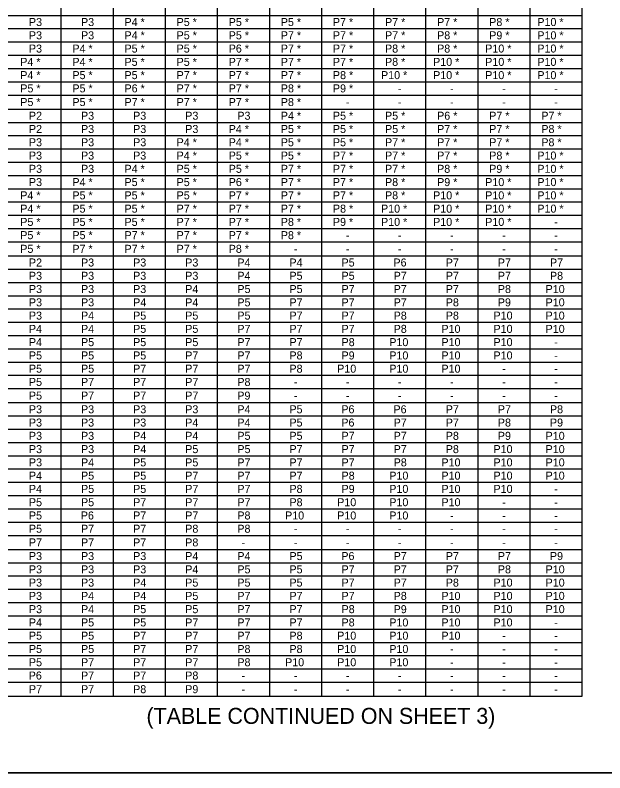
# Model space of a CAD drawing. Extents: x 637580 to 641008, y 294594 to 295782.
# Drawn here: x 638664.4 to 638885.2, y 295202.6 to 295486.5 of the extents above; entities that cross this region are included whole.
import ezdxf

# ---------------------------------------------------------------- set-up
doc = ezdxf.new("R2010")
doc.units = 0
for name, color, linetype in [('1', 7, 'Continuous'), ('2', 7, 'Continuous'), ('3', 7, 'Continuous')]:
    doc.layers.add(name, color=color, linetype=linetype)

msp = doc.modelspace()

# ---------------------------------------------------------------- linework, layer by layer
at = {"layer": '1'}
for p, q in [((638876.73, 295231.34), (638876.73, 295750.63)), ((638681.66, 295231.34), (638681.66, 295735.61)), ((638701.17, 295231.34), (638701.17, 295735.61)), ((638720.67, 295231.34), (638720.67, 295735.61)), ((638740.18, 295231.34), (638740.18, 295735.61)), ((638759.69, 295231.34), (638759.69, 295735.61)), ((638779.2, 295231.34), (638779.2, 295735.61)), ((638798.7, 295231.34), (638798.7, 295735.61)), ((638818.21, 295231.34), (638818.21, 295735.61)), ((638837.72, 295231.34), (638837.72, 295735.61)), ((638857.23, 295231.34), (638857.23, 295735.61)), ((638509.81, 295451.3), (638876.73, 295451.3)), ((638509.81, 295396.31), (638876.73, 295396.31)), ((638509.81, 295341.32), (638876.73, 295341.32)), ((638509.81, 295286.33), (638876.73, 295286.33)), ((638509.81, 295231.34), (638876.73, 295231.34)), ((639247.31, 295202.63), (638461.31, 295202.63)), ((638461.31, 295202.63), (639047.31, 295202.63))]:
    msp.add_line(p, q, dxfattribs=at)
at = {"layer": '2'}
for p, q in [((638536.61, 295486.4), (638876.73, 295486.4)), ((638536.61, 295481.43), (638876.73, 295481.43)), ((638536.61, 295476.45), (638876.73, 295476.45)), ((638536.61, 295471.48), (638876.73, 295471.48)), ((638536.61, 295466.51), (638876.73, 295466.51)), ((638536.61, 295461.54), (638876.73, 295461.54)), ((638536.61, 295456.56), (638876.73, 295456.56)), ((638536.61, 295446.33), (638876.73, 295446.33)), ((638536.61, 295441.35), (638876.73, 295441.35)), ((638536.61, 295436.38), (638876.73, 295436.38)), ((638536.61, 295431.41), (638876.73, 295431.41)), ((638536.61, 295426.44), (638876.73, 295426.44)), ((638536.61, 295421.46), (638876.73, 295421.46)), ((638536.61, 295416.49), (638876.73, 295416.49)), ((638536.61, 295411.52), (638876.73, 295411.52)), ((638536.61, 295406.55), (638876.73, 295406.55)), ((638536.61, 295401.57), (638876.73, 295401.57)), ((638536.61, 295391.34), (638876.73, 295391.34)), ((638536.61, 295386.36), (638876.73, 295386.36)), ((638536.61, 295381.39), (638876.73, 295381.39)), ((638536.61, 295376.42), (638876.73, 295376.42)), ((638536.61, 295371.45), (638876.73, 295371.45)), ((638536.61, 295366.47), (638876.73, 295366.47)), ((638536.61, 295361.5), (638876.73, 295361.5)), ((638536.61, 295356.53), (638876.73, 295356.53)), ((638536.61, 295351.56), (638876.73, 295351.56)), ((638536.61, 295346.58), (638876.73, 295346.58)), ((638536.61, 295336.35), (638876.73, 295336.35)), ((638536.61, 295331.37), (638876.73, 295331.37)), ((638536.61, 295326.4), (638876.73, 295326.4)), ((638536.61, 295321.43), (638876.73, 295321.43)), ((638536.61, 295316.46), (638876.73, 295316.46)), ((638536.61, 295311.48), (638876.73, 295311.48)), ((638536.61, 295306.51), (638876.73, 295306.51)), ((638536.61, 295301.54), (638876.73, 295301.54)), ((638536.61, 295296.57), (638876.73, 295296.57)), ((638536.61, 295291.59), (638876.73, 295291.59)), ((638536.61, 295281.36), (638876.73, 295281.36)), ((638536.61, 295276.38), (638876.73, 295276.38)), ((638536.61, 295271.41), (638876.73, 295271.41)), ((638536.61, 295266.44), (638876.73, 295266.44)), ((638536.61, 295261.47), (638876.73, 295261.47)), ((638536.61, 295256.49), (638876.73, 295256.49)), ((638536.61, 295251.52), (638876.73, 295251.52)), ((638536.61, 295246.55), (638876.73, 295246.55)), ((638536.61, 295241.58), (638876.73, 295241.58)), ((638536.61, 295236.6), (638876.73, 295236.6))]:
    msp.add_line(p, q, dxfattribs=at)

# ---------------------------------------------------------------- texts
at = {"layer": '1'}
for s, p in [('P3', (638669.56, 295482.41)), ('P3', (638689.06, 295482.41)), ('P4 *', (638705.34, 295482.41)), ('P5 *', (638724.85, 295482.41)), ('P5 *', (638744.35, 295482.41)), ('P5 *', (638763.86, 295482.41)), ('P7 *', (638783.37, 295482.41)), ('P7 *', (638802.88, 295482.41)), ('P7 *', (638822.38, 295482.41)), ('P8 *', (638841.89, 295482.41)), ('P10 *', (638859.9, 295482.41)), ('P3', (638669.56, 295477.44)), ('P3', (638689.06, 295477.44)), ('P4 *', (638705.34, 295477.44)), ('P5 *', (638724.85, 295477.44)), ('P5 *', (638744.35, 295477.44)), ('P7 *', (638763.86, 295477.44)), ('P7 *', (638783.37, 295477.44)), ('P7 *', (638802.88, 295477.44)), ('P8 *', (638822.38, 295477.44)), ('P9 *', (638841.89, 295477.44)), ('P10 *', (638859.9, 295477.44)), ('P3', (638669.56, 295472.47)), ('P4 *', (638685.83, 295472.47)), ('P5 *', (638705.34, 295472.47)), ('P5 *', (638724.85, 295472.47)), ('P6 *', (638744.35, 295472.47)), ('P7 *', (638763.86, 295472.47)), ('P7 *', (638783.37, 295472.47)), ('P8 *', (638802.88, 295472.47)), ('P8 *', (638822.38, 295472.47)), ('P10 *', (638840.39, 295472.47)), ('P10 *', (638859.9, 295472.47)), ('P4 *', (638666.32, 295467.49)), ('P4 *', (638685.83, 295467.49)), ('P5 *', (638705.34, 295467.49)), ('P5 *', (638724.85, 295467.49)), ('P7 *', (638744.35, 295467.49)), ('P7 *', (638763.86, 295467.49)), ('P7 *', (638783.37, 295467.49)), ('P8 *', (638802.88, 295467.49)), ('P10 *', (638820.88, 295467.49)), ('P10 *', (638840.39, 295467.49)), ('P10 *', (638859.9, 295467.49)), ('P4 *', (638666.32, 295462.52)), ('P5 *', (638685.83, 295462.52)), ('P5 *', (638705.34, 295462.52)), ('P7 *', (638724.85, 295462.52)), ('P7 *', (638744.35, 295462.52)), ('P7 *', (638763.86, 295462.52)), ('P8 *', (638783.37, 295462.52)), ('P10 *', (638801.38, 295462.52)), ('P10 *', (638820.88, 295462.52)), ('P10 *', (638840.39, 295462.52)), ('P10 *', (638859.9, 295462.52)), ('P5 *', (638666.32, 295457.55)), ('P5 *', (638685.83, 295457.55)), ('P6 *', (638705.34, 295457.55)), ('P7 *', (638724.85, 295457.55)), ('P7 *', (638744.35, 295457.55)), ('P8 *', (638763.86, 295457.55)), ('P9 *', (638783.37, 295457.55)), ('-', (638807.73, 295457.55)), ('-', (638827.23, 295457.55)), ('-', (638846.74, 295457.55)), ('-', (638866.25, 295457.55)), ('P5 *', (638666.32, 295452.43)), ('P5 *', (638685.83, 295452.43)), ('P7 *', (638705.34, 295452.43)), ('P7 *', (638724.85, 295452.43)), ('P7 *', (638744.35, 295452.43)), ('P8 *', (638763.86, 295452.43)), ('-', (638788.22, 295452.43)), ('-', (638807.73, 295452.43)), ('-', (638827.23, 295452.43)), ('-', (638846.74, 295452.43)), ('-', (638866.25, 295452.43)), ('P2', (638669.56, 295447.31)), ('P3', (638689.06, 295447.31)), ('P3', (638708.57, 295447.31)), ('P3', (638728.08, 295447.31)), ('P3', (638747.59, 295447.31)), ('P4 *', (638763.86, 295447.31)), ('P5 *', (638783.37, 295447.31)), ('P5 *', (638802.88, 295447.31)), ('P6 *', (638822.38, 295447.31)), ('P7 *', (638841.89, 295447.31)), ('P7 *', (638861.4, 295447.31)), ('P2', (638669.56, 295442.34)), ('P3', (638689.06, 295442.34)), ('P3', (638708.57, 295442.34)), ('P3', (638728.08, 295442.34)), ('P4 *', (638744.35, 295442.34)), ('P5 *', (638763.86, 295442.34)), ('P5 *', (638783.37, 295442.34)), ('P5 *', (638802.88, 295442.34)), ('P7 *', (638822.38, 295442.34)), ('P7 *', (638841.89, 295442.34)), ('P8 *', (638861.4, 295442.34)), ('P3', (638669.56, 295437.37)), ('P3', (638689.06, 295437.37)), ('P3', (638708.57, 295437.37)), ('P4 *', (638724.85, 295437.37)), ('P4 *', (638744.35, 295437.37)), ('P5 *', (638763.86, 295437.37)), ('P5 *', (638783.37, 295437.37)), ('P7 *', (638802.88, 295437.37)), ('P7 *', (638822.38, 295437.37)), ('P7 *', (638841.89, 295437.37)), ('P8 *', (638861.4, 295437.37)), ('P3', (638669.56, 295432.39)), ('P3', (638689.06, 295432.39)), ('P3', (638708.57, 295432.39)), ('P4 *', (638724.85, 295432.39)), ('P5 *', (638744.35, 295432.39)), ('P5 *', (638763.86, 295432.39)), ('P7 *', (638783.37, 295432.39)), ('P7 *', (638802.88, 295432.39)), ('P7 *', (638822.38, 295432.39)), ('P8 *', (638841.89, 295432.39)), ('P10 *', (638859.9, 295432.39)), ('P3', (638669.56, 295427.42)), ('P3', (638689.06, 295427.42)), ('P4 *', (638705.34, 295427.42)), ('P5 *', (638724.85, 295427.42)), ('P5 *', (638744.35, 295427.42)), ('P7 *', (638763.86, 295427.42)), ('P7 *', (638783.37, 295427.42)), ('P7 *', (638802.88, 295427.42)), ('P8 *', (638822.38, 295427.42)), ('P9 *', (638841.89, 295427.42)), ('P10 *', (638859.9, 295427.42)), ('P3', (638669.56, 295422.45)), ('P4 *', (638685.83, 295422.45)), ('P5 *', (638705.34, 295422.45)), ('P5 *', (638724.85, 295422.45)), ('P6 *', (638744.35, 295422.45)), ('P7 *', (638763.86, 295422.45)), ('P7 *', (638783.37, 295422.45)), ('P8 *', (638802.88, 295422.45)), ('P9 *', (638822.38, 295422.45)), ('P10 *', (638840.39, 295422.45)), ('P10 *', (638859.9, 295422.45)), ('P4 *', (638666.32, 295417.48)), ('P5 *', (638685.83, 295417.48)), ('P5 *', (638705.34, 295417.48)), ('P5 *', (638724.85, 295417.48)), ('P7 *', (638744.35, 295417.48)), ('P7 *', (638763.86, 295417.48)), ('P7 *', (638783.37, 295417.48)), ('P8 *', (638802.88, 295417.48)), ('P10 *', (638820.88, 295417.48)), ('P10 *', (638840.39, 295417.48)), ('P10 *', (638859.9, 295417.48)), ('P4 *', (638666.32, 295412.5)), ('P5 *', (638685.83, 295412.5)), ('P5 *', (638705.34, 295412.5)), ('P7 *', (638724.85, 295412.5)), ('P7 *', (638744.35, 295412.5)), ('P7 *', (638763.86, 295412.5)), ('P8 *', (638783.37, 295412.5)), ('P10 *', (638801.38, 295412.5)), ('P10 *', (638820.88, 295412.5)), ('P10 *', (638840.39, 295412.5)), ('P10 *', (638859.9, 295412.5)), ('P5 *', (638666.32, 295407.53)), ('P5 *', (638685.83, 295407.53)), ('P5 *', (638705.34, 295407.53)), ('P7 *', (638724.85, 295407.53)), ('P7 *', (638744.35, 295407.53)), ('P8 *', (638763.86, 295407.53)), ('P9 *', (638783.37, 295407.53)), ('P10 *', (638801.38, 295407.53)), ('P10 *', (638820.88, 295407.53)), ('P10 *', (638840.39, 295407.53)), ('-', (638866.25, 295407.53)), ('P5 *', (638666.32, 295402.56)), ('P5 *', (638685.83, 295402.56)), ('P7 *', (638705.34, 295402.56)), ('P7 *', (638724.85, 295402.56)), ('P7 *', (638744.35, 295402.56)), ('P8 *', (638763.86, 295402.56)), ('-', (638788.22, 295402.56)), ('-', (638807.73, 295402.56)), ('-', (638827.23, 295402.56)), ('-', (638846.74, 295402.56)), ('-', (638866.25, 295402.56)), ('P5 *', (638666.32, 295397.44)), ('P7 *', (638685.83, 295397.44)), ('P7 *', (638705.34, 295397.44)), ('P7 *', (638724.85, 295397.44)), ('P8 *', (638744.35, 295397.44)), ('-', (638768.71, 295397.44)), ('-', (638788.22, 295397.44)), ('-', (638807.73, 295397.44)), ('-', (638827.23, 295397.44)), ('-', (638846.74, 295397.44)), ('-', (638866.25, 295397.44)), ('P2', (638669.56, 295392.32)), ('P3', (638689.06, 295392.32)), ('P3', (638708.57, 295392.32)), ('P3', (638728.08, 295392.32)), ('P4', (638747.59, 295392.32)), ('P4', (638767.09, 295392.32)), ('P5', (638786.6, 295392.32)), ('P6', (638806.03, 295392.32)), ('P7', (638825.62, 295392.32)), ('P7', (638845.12, 295392.32)), ('P7', (638864.63, 295392.32)), ('P3', (638669.56, 295387.35)), ('P3', (638689.06, 295387.35)), ('P3', (638708.57, 295387.35)), ('P3', (638728.08, 295387.35)), ('P4', (638747.59, 295387.35)), ('P5', (638767.09, 295387.35)), ('P5', (638786.6, 295387.35)), ('P7', (638806.11, 295387.35)), ('P7', (638825.62, 295387.35)), ('P7', (638845.12, 295387.35)), ('P8', (638864.63, 295387.35)), ('P3', (638669.56, 295382.38)), ('P3', (638689.06, 295382.38)), ('P3', (638708.57, 295382.38)), ('P4', (638728.08, 295382.38)), ('P5', (638747.59, 295382.38)), ('P5', (638767.09, 295382.38)), ('P7', (638786.6, 295382.38)), ('P7', (638806.11, 295382.38)), ('P7', (638825.62, 295382.38)), ('P8', (638845.12, 295382.38)), ('P10', (638863, 295382.38)), ('P3', (638669.56, 295377.4)), ('P3', (638689.06, 295377.4)), ('P4', (638708.57, 295377.4)), ('P4', (638728.08, 295377.4)), ('P5', (638747.59, 295377.4)), ('P7', (638767.09, 295377.4)), ('P7', (638786.6, 295377.4)), ('P7', (638806.11, 295377.4)), ('P8', (638825.62, 295377.4)), ('P9', (638845.11, 295377.4)), ('P10', (638863, 295377.4)), ('P3', (638669.56, 295372.43)), ('P4', (638689.06, 295372.43)), ('P5', (638708.57, 295372.43)), ('P5', (638728.08, 295372.43)), ('P5', (638747.59, 295372.43)), ('P7', (638767.09, 295372.43)), ('P7', (638786.6, 295372.43)), ('P8', (638806.11, 295372.43)), ('P8', (638825.62, 295372.43)), ('P10', (638843.49, 295372.43)), ('P10', (638863, 295372.43)), ('P4', (638669.56, 295367.46)), ('P4', (638689.06, 295367.46)), ('P5', (638708.57, 295367.46)), ('P5', (638728.08, 295367.46)), ('P7', (638747.59, 295367.46)), ('P7', (638767.09, 295367.46)), ('P7', (638786.6, 295367.46)), ('P8', (638806.11, 295367.46)), ('P10', (638823.99, 295367.46)), ('P10', (638843.49, 295367.46)), ('P10', (638863, 295367.46)), ('P4', (638669.56, 295362.49)), ('P5', (638689.06, 295362.49)), ('P5', (638708.57, 295362.49)), ('P5', (638728.08, 295362.49)), ('P7', (638747.59, 295362.49)), ('P7', (638767.09, 295362.49)), ('P8', (638786.6, 295362.49)), ('P10', (638804.48, 295362.49)), ('P10', (638823.99, 295362.49)), ('P10', (638843.49, 295362.49)), ('-', (638866.25, 295362.49)), ('P5', (638669.56, 295357.51)), ('P5', (638689.06, 295357.51)), ('P5', (638708.57, 295357.51)), ('P7', (638728.08, 295357.51)), ('P7', (638747.59, 295357.51)), ('P8', (638767.09, 295357.51)), ('P9', (638786.59, 295357.51)), ('P10', (638804.48, 295357.51)), ('P10', (638823.99, 295357.51)), ('P10', (638843.49, 295357.51)), ('-', (638866.25, 295357.51)), ('P5', (638669.56, 295352.54)), ('P5', (638689.06, 295352.54)), ('P7', (638708.57, 295352.54)), ('P7', (638728.08, 295352.54)), ('P7', (638747.59, 295352.54)), ('P8', (638767.09, 295352.54)), ('P10', (638784.97, 295352.54)), ('P10', (638804.48, 295352.54)), ('P10', (638823.99, 295352.54)), ('-', (638846.74, 295352.54)), ('-', (638866.25, 295352.54)), ('P5', (638669.56, 295347.57)), ('P7', (638689.06, 295347.57)), ('P7', (638708.57, 295347.57)), ('P7', (638728.08, 295347.57)), ('P8', (638747.59, 295347.57)), ('-', (638768.71, 295347.57)), ('-', (638788.22, 295347.57)), ('-', (638807.73, 295347.57)), ('-', (638827.23, 295347.57)), ('-', (638846.74, 295347.57)), ('-', (638866.25, 295347.57)), ('P5', (638669.56, 295342.45)), ('P7', (638689.06, 295342.45)), ('P7', (638708.57, 295342.45)), ('P7', (638728.08, 295342.45)), ('P9', (638747.57, 295342.45)), ('-', (638768.71, 295342.45)), ('-', (638788.22, 295342.45)), ('-', (638807.73, 295342.45)), ('-', (638827.23, 295342.45)), ('-', (638846.74, 295342.45)), ('-', (638866.25, 295342.45)), ('P3', (638669.56, 295337.33)), ('P3', (638689.06, 295337.33)), ('P3', (638708.57, 295337.33)), ('P3', (638728.08, 295337.33)), ('P4', (638747.59, 295337.33)), ('P5', (638767.09, 295337.33)), ('P6', (638786.52, 295337.33)), ('P6', (638806.03, 295337.33)), ('P7', (638825.62, 295337.33)), ('P7', (638845.12, 295337.33)), ('P8', (638864.63, 295337.33)), ('P3', (638669.56, 295332.36)), ('P3', (638689.06, 295332.36)), ('P3', (638708.57, 295332.36)), ('P4', (638728.08, 295332.36)), ('P4', (638747.59, 295332.36)), ('P5', (638767.09, 295332.36)), ('P6', (638786.52, 295332.36)), ('P7', (638806.11, 295332.36)), ('P7', (638825.62, 295332.36)), ('P8', (638845.12, 295332.36)), ('P9', (638864.62, 295332.36)), ('P3', (638669.56, 295327.39)), ('P3', (638689.06, 295327.39)), ('P4', (638708.57, 295327.39)), ('P4', (638728.08, 295327.39)), ('P5', (638747.59, 295327.39)), ('P5', (638767.09, 295327.39)), ('P7', (638786.6, 295327.39)), ('P7', (638806.11, 295327.39)), ('P8', (638825.62, 295327.39)), ('P9', (638845.11, 295327.39)), ('P10', (638863, 295327.39)), ('P3', (638669.56, 295322.41)), ('P3', (638689.06, 295322.41)), ('P4', (638708.57, 295322.41)), ('P5', (638728.08, 295322.41)), ('P5', (638747.59, 295322.41)), ('P7', (638767.09, 295322.41)), ('P7', (638786.6, 295322.41)), ('P7', (638806.11, 295322.41)), ('P8', (638825.62, 295322.41)), ('P10', (638843.49, 295322.41)), ('P10', (638863, 295322.41)), ('P3', (638669.56, 295317.44)), ('P4', (638689.06, 295317.44)), ('P5', (638708.57, 295317.44)), ('P5', (638728.08, 295317.44)), ('P7', (638747.59, 295317.44)), ('P7', (638767.09, 295317.44)), ('P7', (638786.6, 295317.44)), ('P8', (638806.11, 295317.44)), ('P10', (638823.99, 295317.44)), ('P10', (638843.49, 295317.44)), ('P10', (638863, 295317.44)), ('P4', (638669.56, 295312.47)), ('P5', (638689.06, 295312.47)), ('P5', (638708.57, 295312.47)), ('P7', (638728.08, 295312.47)), ('P7', (638747.59, 295312.47)), ('P7', (638767.09, 295312.47)), ('P8', (638786.6, 295312.47)), ('P10', (638804.48, 295312.47)), ('P10', (638823.99, 295312.47)), ('P10', (638843.49, 295312.47)), ('P10', (638863, 295312.47)), ('P4', (638669.56, 295307.5)), ('P5', (638689.06, 295307.5)), ('P5', (638708.57, 295307.5)), ('P7', (638728.08, 295307.5)), ('P7', (638747.59, 295307.5)), ('P8', (638767.09, 295307.5)), ('P9', (638786.59, 295307.5)), ('P10', (638804.48, 295307.5)), ('P10', (638823.99, 295307.5)), ('P10', (638843.49, 295307.5)), ('-', (638866.25, 295307.5)), ('P5', (638669.56, 295302.52)), ('P5', (638689.06, 295302.52)), ('P7', (638708.57, 295302.52)), ('P7', (638728.08, 295302.52)), ('P7', (638747.59, 295302.52)), ('P8', (638767.09, 295302.52)), ('P10', (638784.97, 295302.52)), ('P10', (638804.48, 295302.52)), ('P10', (638823.99, 295302.52)), ('-', (638846.74, 295302.52)), ('-', (638866.25, 295302.52)), ('P5', (638669.56, 295297.55)), ('P6', (638688.98, 295297.55)), ('P7', (638708.57, 295297.55)), ('P7', (638728.08, 295297.55)), ('P8', (638747.59, 295297.55)), ('P10', (638765.46, 295297.55)), ('P10', (638784.97, 295297.55)), ('P10', (638804.48, 295297.55)), ('-', (638827.23, 295297.55)), ('-', (638846.74, 295297.55)), ('-', (638866.25, 295297.55)), ('P5', (638669.56, 295292.58)), ('P7', (638689.06, 295292.58)), ('P7', (638708.57, 295292.58)), ('P8', (638728.08, 295292.58)), ('P8', (638747.59, 295292.58)), ('-', (638768.71, 295292.58)), ('-', (638788.22, 295292.58)), ('-', (638807.73, 295292.58)), ('-', (638827.23, 295292.58)), ('-', (638846.74, 295292.58)), ('-', (638866.25, 295292.58)), ('P7', (638669.56, 295287.46)), ('P7', (638689.06, 295287.46)), ('P7', (638708.57, 295287.46)), ('P8', (638728.08, 295287.46)), ('-', (638749.2, 295287.46)), ('-', (638768.71, 295287.46)), ('-', (638788.22, 295287.46)), ('-', (638807.73, 295287.46)), ('-', (638827.23, 295287.46)), ('-', (638846.74, 295287.46)), ('-', (638866.25, 295287.46)), ('P3', (638669.56, 295282.34)), ('P3', (638689.06, 295282.34)), ('P3', (638708.57, 295282.34)), ('P4', (638728.08, 295282.34)), ('P4', (638747.59, 295282.34)), ('P5', (638767.09, 295282.34)), ('P6', (638786.52, 295282.34)), ('P7', (638806.11, 295282.34)), ('P7', (638825.62, 295282.34)), ('P7', (638845.12, 295282.34)), ('P9', (638864.62, 295282.34)), ('P3', (638669.56, 295277.37)), ('P3', (638689.06, 295277.37)), ('P3', (638708.57, 295277.37)), ('P4', (638728.08, 295277.37)), ('P5', (638747.59, 295277.37)), ('P5', (638767.09, 295277.37)), ('P7', (638786.6, 295277.37)), ('P7', (638806.11, 295277.37)), ('P7', (638825.62, 295277.37)), ('P8', (638845.12, 295277.37)), ('P10', (638863, 295277.37)), ('P3', (638669.56, 295272.4)), ('P3', (638689.06, 295272.4)), ('P4', (638708.57, 295272.4)), ('P5', (638728.08, 295272.4)), ('P5', (638747.59, 295272.4)), ('P5', (638767.09, 295272.4)), ('P7', (638786.6, 295272.4)), ('P7', (638806.11, 295272.4)), ('P8', (638825.62, 295272.4)), ('P10', (638843.49, 295272.4)), ('P10', (638863, 295272.4)), ('P3', (638669.56, 295267.42)), ('P4', (638689.06, 295267.42)), ('P4', (638708.57, 295267.42)), ('P5', (638728.08, 295267.42)), ('P7', (638747.59, 295267.42)), ('P7', (638767.09, 295267.42)), ('P7', (638786.6, 295267.42)), ('P8', (638806.11, 295267.42)), ('P10', (638823.99, 295267.42)), ('P10', (638843.49, 295267.42)), ('P10', (638863, 295267.42)), ('P3', (638669.56, 295262.45)), ('P4', (638689.06, 295262.45)), ('P5', (638708.57, 295262.45)), ('P5', (638728.08, 295262.45)), ('P7', (638747.59, 295262.45)), ('P7', (638767.09, 295262.45)), ('P8', (638786.6, 295262.45)), ('P9', (638806.1, 295262.45)), ('P10', (638823.99, 295262.45)), ('P10', (638843.49, 295262.45)), ('P10', (638863, 295262.45)), ('P4', (638669.56, 295257.48)), ('P5', (638689.06, 295257.48)), ('P5', (638708.57, 295257.48)), ('P7', (638728.08, 295257.48)), ('P7', (638747.59, 295257.48)), ('P7', (638767.09, 295257.48)), ('P8', (638786.6, 295257.48)), ('P10', (638804.48, 295257.48)), ('P10', (638823.99, 295257.48)), ('P10', (638843.49, 295257.48)), ('-', (638866.25, 295257.48)), ('P5', (638669.56, 295252.51)), ('P5', (638689.06, 295252.51)), ('P7', (638708.57, 295252.51)), ('P7', (638728.08, 295252.51)), ('P7', (638747.59, 295252.51)), ('P8', (638767.09, 295252.51)), ('P10', (638784.97, 295252.51)), ('P10', (638804.48, 295252.51)), ('P10', (638823.99, 295252.51)), ('-', (638846.74, 295252.51)), ('-', (638866.25, 295252.51)), ('P5', (638669.56, 295247.53)), ('P5', (638689.06, 295247.53)), ('P7', (638708.57, 295247.53)), ('P7', (638728.08, 295247.53)), ('P8', (638747.59, 295247.53)), ('P8', (638767.09, 295247.53)), ('P10', (638784.97, 295247.53)), ('P10', (638804.48, 295247.53)), ('-', (638827.23, 295247.53)), ('-', (638846.74, 295247.53)), ('-', (638866.25, 295247.53)), ('P5', (638669.56, 295242.56)), ('P7', (638689.06, 295242.56)), ('P7', (638708.57, 295242.56)), ('P7', (638728.08, 295242.56)), ('P8', (638747.59, 295242.56)), ('P10', (638765.46, 295242.56)), ('P10', (638784.97, 295242.56)), ('P10', (638804.48, 295242.56)), ('-', (638827.23, 295242.56)), ('-', (638846.74, 295242.56)), ('-', (638866.25, 295242.56)), ('P6', (638669.47, 295237.59)), ('P7', (638689.06, 295237.59)), ('P7', (638708.57, 295237.59)), ('P8', (638728.08, 295237.59)), ('-', (638749.2, 295237.59)), ('-', (638768.71, 295237.59)), ('-', (638788.22, 295237.59)), ('-', (638807.73, 295237.59)), ('-', (638827.23, 295237.59)), ('-', (638846.74, 295237.59)), ('-', (638866.25, 295237.59)), ('P7', (638669.56, 295232.47)), ('P7', (638689.06, 295232.47)), ('P8', (638708.57, 295232.47)), ('P9', (638728.07, 295232.47)), ('-', (638749.2, 295232.47)), ('-', (638768.71, 295232.47)), ('-', (638788.22, 295232.47)), ('-', (638807.73, 295232.47)), ('-', (638827.23, 295232.47)), ('-', (638846.74, 295232.47)), ('-', (638866.25, 295232.47))]:
    msp.add_text(s, height=3, dxfattribs=at).set_placement(p)
at = {"layer": '3'}
msp.add_text('(TABLE CONTINUED ON SHEET 3)', height=6, dxfattribs=at).set_placement((638713.56, 295220.97))

doc.saveas('drawing.dxf')
